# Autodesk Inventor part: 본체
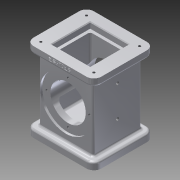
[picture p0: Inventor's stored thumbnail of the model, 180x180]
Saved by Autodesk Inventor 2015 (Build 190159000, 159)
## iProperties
Created: 2017-08
Part Number: 본체
Material: 알루미늄 6061
Document SubType Name: Modeling
Designer: Administrator
Density: 2.7 g/cm^3
Appearance: 알루미늄 - 평지
Mass: 869.111 g
Surface Area: 642.217 cm^2
Volume: 321.893 cm^3
Author: Administrator
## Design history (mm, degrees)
sketch "스케치1"
  geometry: L1 (-46, 41)-(46, 41); L2 (46, 41)-(46, -41); L3 (46, -41)-(-46, -41); L4 (-46, -41)-(-46, 41); L5 (-46, 41)-(46, -41); 2 further points
  constraints: 10 end point, 2 parallel, 1 coincident, 1 horizontal, 1 midpoint, 1 perpendicular
  dimensions: "d0" = 92 distance of L2.end L3.end; "d1" = 82 distance of L1.end L2.end
extrude "돌출1" new body sketch "스케치1" distance "d2" = 10; taper "d3" = 0 deg
sketch "스케치2"
  geometry: L1 (37, -33)-(-37, -33); L2 (-37, -33)-(-37, 33); L3 (-37, 33)-(37, 33); L4 (37, 33)-(37, -33); L5 (37, -33)-(-37, 33); 2 further points
  constraints: 10 end point, 2 parallel, 1 coincident, 1 horizontal, 1 midpoint, 1 perpendicular
  dimensions: "d4" = 74 distance of L1.start L1.end; "d5" = 66 distance of L1.end L2.end
extrude "돌출2" join sketch "스케치2" distance "d6" = 88; taper "d7" = 0 deg
sketch "스케치3"
  geometry: L1 (46, -41)-(-46, -41); L2 (-46, -41)-(-46, 41); L3 (-46, 41)-(46, 41); L4 (46, 41)-(46, -41); 1 further point
  constraints: 8 end point, 2 parallel, 1 horizontal, 1 perpendicular
extrude "돌출3" join sketch "스케치3" distance "d8" = 10; taper "d9" = 0 deg
sketch "스케치5"
  geometry: L1 (54, -56.881)-(54, 67.394); L2 (10, -33)-(98, -33) reference; L3 (10, 33)-(98, 33) reference; L4 (54, -33)-(89, -33); L5 (89, -30)-(89, -33); L6 (89, -30)-(78, -30); L7 (78, -30)-(78, 30); L8 (78, 30)-(89, 30); L9 (89, 30)-(89, 33); L10 (89, 33)-(54, 33); L11 (54, -33)-(54, 33); 1 further point
  constraints: 18 end point, 5 perpendicular, 2 midpoint, 2 point on line, 1 horizontal, 1 vertical
  dimensions: "d15" = 54 distance from line of point (0, 0) L1; "d16" = 70 diameter of L5 L1; "d17" = 48 diameter of L7 L1; "d18" = 3 distance of L5.start L4.end; "d19" = 70 diameter of L9 L1; "d20" = 3 distance of L8.end L9.end
revolve "회전1" sketch "스케치5" stored, may be unused: angle "d21" = 90 deg
sketch "스케치6"
  geometry: L1 (-24, -24)-(24, -24); L2 (24, -24)-(24, 24); L3 (24, 24)-(-24, 24); L4 (-24, 24)-(-24, -24); L5 (-24, -24)-(24, 24); 2 further points
  constraints: 10 end point, 2 parallel, 1 coincident, 1 horizontal, 1 midpoint, 1 perpendicular
  dimensions: "d22" = 48 distance of L1.end L2.end; "d23" = 48 distance of L2.end L3.end
extrude "돌출4" cut sketch "스케치6" distance "d24" = 16; taper "d25" = 0 deg
sketch "스케치7"
  geometry: L1 (26, 26)-(-26, 26); L2 (-26, 26)-(-26, -26); L3 (-26, -26)-(26, -26); L4 (26, -26)-(26, 26); L5 (26, 26)-(-26, -26); 2 further points
  constraints: 10 end point, 2 parallel, 1 coincident, 1 horizontal, 1 midpoint, 1 perpendicular
  dimensions: "d26" = 52 distance of L3.end L1.start; "d27" = 52 distance of L2.end L3.end
extrude "돌출5" cut sketch "스케치7" distance "d28" = 8; taper "d29" = 0 deg
sketch "스케치8"
  geometry: L1 (22, 22)-(-22, 22); L2 (-22, 22)-(-22, -22); L3 (-22, -22)-(22, -22); L4 (22, -22)-(22, 22); L5 (22, 22)-(-22, -22); 2 further points
  constraints: 10 end point, 2 parallel, 1 coincident, 1 horizontal, 1 midpoint, 1 perpendicular
  dimensions: "d30" = 44 distance of L1.end L2.end; "d31" = 44 distance of L2.end L3.end
extrude "돌출6" cut sketch "스케치8" distance "d32" = 74; taper "d33" = 0 deg
sketch "스케치9" dims "d34" = 58
  geometry: L1 (0, 0)-(0, 41.751); C1 r 35 at (0, 0) reference; 5 further points
  constraints: 2 end point, 1 coincident, 1 point on line, 1 vertical, 1 vertical alignment, 7 other
  dimensions: "d37" = 360 deg dimension on L1.start point (0, 29) (derived)
hole "구멍1" sketch "스케치9" at (0, 29), (-29, 0), (0, -29), (29, 0) diameter "d39" = 3.242; stored, may be unused: countersink angle "d43" = 90 deg, drill point angle "d45" = 118 deg; dims "d40" = 4, "d41" = 4, "d42" = 2, "d44" = 6
sketch "스케치10"
  geometry: 5 further points
  dimensions: "d48" = 72 distance of point (-36, -31) point (36, -31); "d49" = 36 horizontal distance of point (36, -31) point (0, 0); "d50" = 72 distance of point (36, 31) point (-36, 31); "d51" = 36 horizontal distance of point (0, 0) point (36, 31); "d52" = 62 distance of point (-36, -31) point (-36, 31); "d53" = 31 vertical distance of point (-36, 31) point (0, 0); "d54" = 62 distance of point (36, -31) point (36, 31); "d55" = 31 vertical distance of point (0, 0) point (36, 31)
hole "구멍2" sketch "스케치10" at (36, -31), (-36, -31), (36, 31), (-36, 31) diameter "d56" = 3.242; stored, may be unused: countersink angle "d60" = 90 deg, drill point angle "d62" = 118 deg; dims "d57" = 4, "d58" = 4, "d59" = 2, "d61" = 6
node "작업 평면1"
sketch "스케치11" dims "d15" = 54, "d16" = 70, "d17" = 48, "d18" = 3, "d19" = 70, "d20" = 3
  geometry: L1 (33, -10)-(33, 116.657); 2 further points
  constraints: 2 end point, 2 point on line, 1 vertical
  dimensions: "d64" = 38 distance of L1.start point (33, 28); "d65" = 42 distance of point (33, 28) point (33, 70)
hole "구멍3" sketch "스케치11" at (33, 28), (33, 70) diameter "d66" = 4.134; stored, may be unused: countersink angle "d70" = 90 deg, drill point angle "d72" = 118 deg; dims "d67" = 25, "d68" = 4, "d69" = 2, "d71" = 30
node "작업 평면2"
sketch "스케치12"
  geometry: L1 (92, 0)-(0, 0) reference; L2 (92, 0)-(92, 10) reference; L3 (0, 10)-(92, 10) reference; L4 (0, 0)-(0, 10) reference; L5 (0, 10.9)-(92.44, 10.9); L6 (92.44, 10.9)-(92.44, 1.1); L7 (92.44, 1.1)-(0, 1.1); L8 (0, 1.1)-(0, 10.9); L9 (46, -98)-(46, 36.846); L10 (0, 6)-(92.44, 6)
  constraints: 4 end point, 2 midpoint, 1 vertical, 2 other
  dimensions: "d74" = 4 distance between parallel lines of L3 L10; "d75" = 46 distance from line of L9 L5.start
feature "엠보싱1" sketch "스케치12" dims "d0" = 92, "d1" = 82, "d76" = 0.5, "d77" = 0
chamfer "모따기1" distance "d78" = 1; stored, may be unused: second distance "d79" = 2, angle "d80" = 45 deg
fillet "모깎기1" dims "d81" = 3
fillet "모깎기2" dims "d82" = 3
fillet "모깎기3" dims "d83" = 3
fillet "모깎기4" dims "d84" = 3
fillet "모깎기5" dims "d85" = 3
fillet "모깎기6" dims "d86" = 10
node "솔리드1"
mirror "대칭1"
mirror "대칭2"
node "투영된 루프1"
other parameters: "d63" = -54, "d73" = 0
